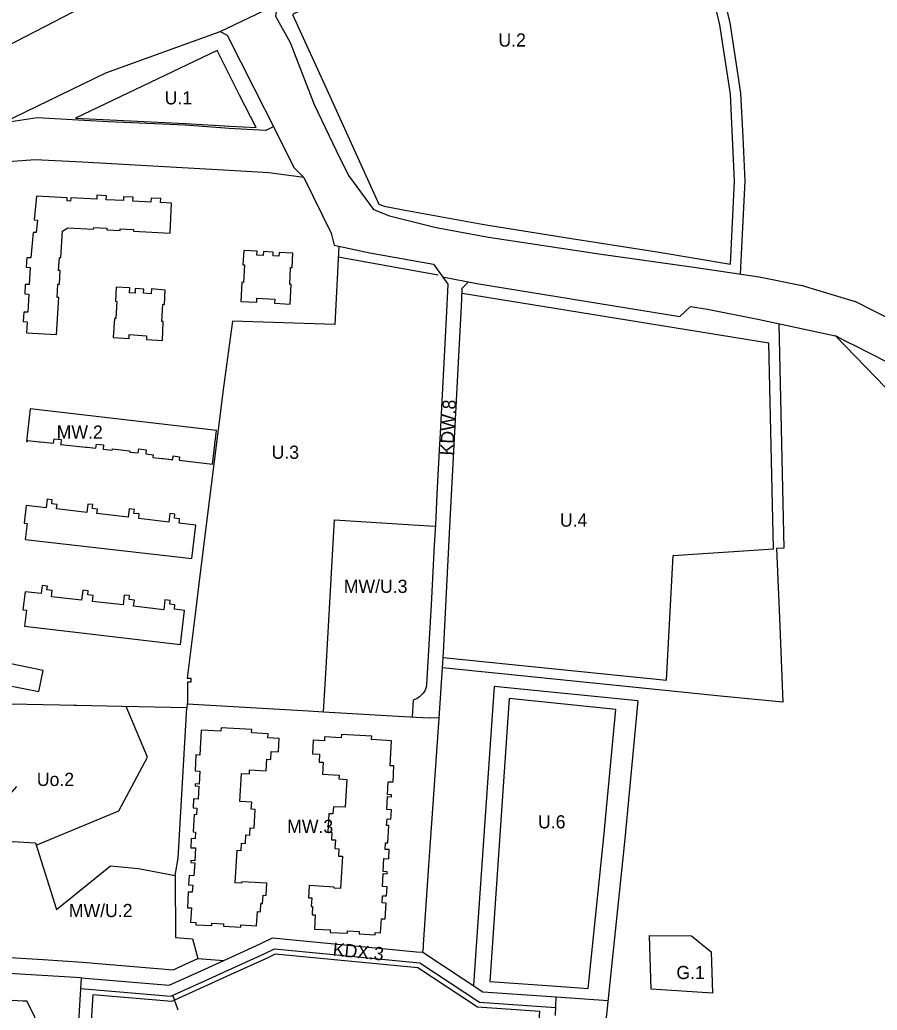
# Model space of a CAD drawing. Extents: x 7427074 to 7428708, y 5545888 to 5547145.
# Drawn here: x 7427562.4 to 7427887.2, y 5546349.6 to 5546725 of the extents above; entities that cross this region are included whole.
import ezdxf

# ---------------------------------------------------------------- set-up
doc = ezdxf.new("R2010")
doc.units = 0
for name, color, linetype in [('linie_rozgraniczajace', 7, 'Continuous'), ('linie_zabudowy_nieprzekraczalne', 7, 'Continuous'), ('linie_zabudowy_obowiazujace', 7, 'Continuous'), ('oznaczenia_przeznaczen', 7, 'Continuous')]:
    doc.layers.add(name, color=color, linetype=linetype)

msp = doc.modelspace()

# ---------------------------------------------------------------- linework, layer by layer
at = {"layer": 'linie_rozgraniczajace'}
for p, q in [((7427655.48, 5546683.03), (7427658.46, 5546684.55)), ((7427729.83, 5546619.05), (7427730.05, 5546623.33)), ((7427735.55, 5546625.11), (7427812.43, 5546612.51)), ((7427725.37, 5546532.76), (7427729.83, 5546619.05)), ((7427715.52, 5546533.36), (7427719.83, 5546533.1)), ((7427793.97, 5546467.06), (7427742.1, 5546472.34)), ((7427577.73, 5546465.23), (7427571.25, 5546465.36)), ((7427583.01, 5546465.12), (7427577.73, 5546465.23)), ((7427583.81, 5546465.1), (7427583.01, 5546465.12)), ((7427600.98, 5546464.74), (7427583.81, 5546465.1)), ((7427711.44, 5546467.07), (7427711.1, 5546460.77)), ((7427796.61, 5546466.79), (7427793.97, 5546467.06)), ((7427625.7, 5546464.21), (7427600.98, 5546464.74)), ((7427622.91, 5546416.05), (7427625.7, 5546464.21)), ((7427715.02, 5546460.56), (7427717.67, 5546460.41)), ((7427721.22, 5546460.22), (7427717.67, 5546460.41)), ((7427622.4, 5546407.21), (7427622.91, 5546416.05)), ((7427621.29, 5546400.65), (7427622.4, 5546407.21)), ((7427576.26, 5546387.77), (7427596.75, 5546404.32)), ((7427596.75, 5546404.32), (7427607.32, 5546403.27)), ((7427607.32, 5546403.27), (7427621.29, 5546400.65)), ((7427658.84, 5546372.88), (7427713.94, 5546367.53)), ((7427712.66, 5546371.67), (7427715.15, 5546371.52)), ((7427715.15, 5546371.52), (7427737.83, 5546356.58)), ((7427713.94, 5546367.53), (7427736.51, 5546352.66)), ((7427585.66, 5546361.85), (7427583.79, 5546331.94)), ((7427572.14, 5546338.65), (7427565.07, 5546353.09)), ((7427622.4, 5546349.58), (7427620.32, 5546355.24)), ((7427765.34, 5546347.61), (7427765.55, 5546354.65))]:
    msp.add_line(p, q, dxfattribs=at)
for points in [[(7427400.2, 5546611.86), (7427442.19, 5546643.82), (7427480.94, 5546671.03), (7427524.86, 5546698.24), (7427615.03, 5546744.99), (7427747.54, 5546812.47), (7427897.12, 5546887.45), (7428084.42, 5546980.69), (7428179.45, 5547028.08)], [(7427638.36, 5546720.62), (7427657.58, 5546729.8), (7427659.95, 5546730.93), (7427768.59, 5546782.79), (7427797.99, 5546801.02), (7427860.58, 5546832.47), (7427996.31, 5546900.83), (7428036.08, 5546920.85), (7428083.92, 5546944.95), (7428147.58, 5546977.01), (7428190.12, 5546998.43)], [(7427835.49, 5546628.61), (7427836.35, 5546646.31), (7427837.2, 5546663.8), (7427836.41, 5546680.51), (7427835.63, 5546697.23), (7427833.57, 5546710.55), (7427831.52, 5546723.86), (7427827.87, 5546739.27), (7427824.22, 5546754.69), (7427820.57, 5546770.1), (7427816.92, 5546785.51), (7427810.97, 5546807.54)], [(7427659.95, 5546730.93), (7427659.28, 5546726.41), (7427664.87, 5546716.42), (7427673.88, 5546692.97), (7427682.3, 5546675.51), (7427686.9, 5546666), (7427696.35, 5546653.1), (7427702.46, 5546650.69), (7427720.19, 5546646.26), (7427739.95, 5546642.68), (7427782.69, 5546636.21), (7427817.72, 5546631.23), (7427842.55, 5546627.57), (7427858.78, 5546624.29), (7427878.85, 5546618.23)], [(7427364.2, 5546554.17), (7427395.05, 5546577.83), (7427421.52, 5546598.13), (7427443.89, 5546615.25), (7427461.19, 5546627.88), (7427476.45, 5546638.44), (7427486.49, 5546645.1), (7427491.66, 5546648.44), (7427499.68, 5546653.51), (7427507.23, 5546658.17), (7427516.35, 5546663.63), (7427526.34, 5546669.42), (7427534.09, 5546673.78), (7427540.36, 5546677.22), (7427550.02, 5546682.6), (7427555.89, 5546685.9), (7427594.96, 5546704.86), (7427638.36, 5546720.62)], [(7427638.36, 5546720.62), (7427640.95, 5546719.15), (7427651, 5546699.2), (7427659.1, 5546683.29)], [(7427655.48, 5546683.03), (7427641.71, 5546683.78), (7427625.07, 5546685.04), (7427596.01, 5546686.32), (7427586.83, 5546686.79), (7427569.02, 5546687.86), (7427555.86, 5546685.88)], [(7427659.1, 5546683.29), (7427666.24, 5546669.07), (7427670.02, 5546665.3), (7427680.36, 5546644.15), (7427681.53, 5546639.53)], [(7427670.02, 5546665.3), (7427656.69, 5546667.04), (7427641.81, 5546667.88), (7427623.85, 5546668.9), (7427585.97, 5546670.99), (7427568.18, 5546671.93), (7427549.37, 5546670.57), (7427543.89, 5546667.66), (7427525, 5546659.31), (7427503.72, 5546645.77), (7427469.2, 5546620.79), (7427458.78, 5546615.05), (7427424.98, 5546588.18), (7427381.06, 5546554.49)], [(7427683.22, 5546639.18), (7427681.71, 5546609.54), (7427642.94, 5546610.74), (7427639.58, 5546585.77), (7427634.91, 5546548.56), (7427630.5, 5546513.34), (7427628.92, 5546500.76), (7427625.74, 5546475.42), (7427627.14, 5546475.48), (7427627.2, 5546473.98), (7427625.9, 5546473.93), (7427625.87, 5546466.07), (7427625.84, 5546465.71), (7427625.7, 5546464.21)], [(7427681.53, 5546639.53), (7427694.95, 5546636.74), (7427719.07, 5546632.44), (7427724.6, 5546624.85)], [(7427722.6, 5546627.6), (7427735.55, 5546625.11)], [(7427724.6, 5546624.85), (7427723.94, 5546611.92), (7427721.55, 5546565.94), (7427721.45, 5546564.3), (7427720.44, 5546545.17), (7427719.86, 5546533.63), (7427719.36, 5546525.82), (7427718.19, 5546503.3), (7427716.54, 5546473.03), (7427716.36, 5546471.86), (7427715.79, 5546470.67), (7427715.22, 5546469.82), (7427714.58, 5546469.09), (7427713.86, 5546468.36), (7427712.91, 5546467.7), (7427711.44, 5546467.07)], [(7427730.05, 5546623.33), (7427732.42, 5546625.71)], [(7427812.43, 5546612.51), (7427816.54, 5546616.39), (7427822.91, 5546615.31)], [(7427822.91, 5546615.31), (7427842.03, 5546611.49), (7427871.42, 5546605.18), (7427894.13, 5546581.67)], [(7427946.45, 5546578.21), (7427924.84, 5546593.37), (7427918.6, 5546597.94), (7427906.55, 5546604.1), (7427890.37, 5546612.47), (7427886.58, 5546614.33), (7427878.85, 5546618.23)], [(7427849.96, 5546609.79), (7427851.93, 5546524.74), (7427849.13, 5546524.54), (7427850.22, 5546498.26), (7427851.55, 5546466.3)], [(7427936.76, 5546566.69), (7427916.1, 5546581.17), (7427910.7, 5546585.13), (7427907.42, 5546586.81), (7427899.69, 5546590.77), (7427883.62, 5546599.07), (7427879.89, 5546600.9), (7427875.47, 5546603.13), (7427871.42, 5546605.18)], [(7427677.45, 5546462.71), (7427678.15, 5546475.19), (7427678.53, 5546481.64), (7427681.66, 5546535.43), (7427715.52, 5546533.36)], [(7427721.22, 5546460.22), (7427722.53, 5546479.36), (7427722.92, 5546485.17), (7427725.37, 5546532.76)], [(7427851.55, 5546466.3), (7427827.82, 5546468.68), (7427794.47, 5546472.03), (7427722.53, 5546479.36)], [(7427742.1, 5546472.34), (7427735.1, 5546370.15), (7427734.33, 5546358.89)], [(7427571.25, 5546465.36), (7427558.99, 5546465.62), (7427552.3, 5546465.76), (7427547.71, 5546446.24)], [(7427625.84, 5546465.71), (7427671.82, 5546463.04), (7427677.45, 5546462.71), (7427707.88, 5546460.95), (7427715.02, 5546460.56)], [(7427796.61, 5546466.79), (7427791.59, 5546414.49), (7427783.21, 5546333.36)], [(7427715.15, 5546371.52), (7427715.28, 5546373.4), (7427715.35, 5546374.48), (7427717.4, 5546404.44), (7427717.88, 5546411.51), (7427721.22, 5546460.22)], [(7427557.29, 5546413.6), (7427568.29, 5546413.01), (7427576.26, 5546387.77)], [(7427621.29, 5546400.65), (7427621.43, 5546377.11), (7427627.81, 5546376.68), (7427629.81, 5546369.13)], [(7427639.63, 5546368.43), (7427653.51, 5546374.75), (7427658.11, 5546376.97)], [(7427658.11, 5546376.97), (7427712.66, 5546371.67)], [(7427641.29, 5546364.79), (7427655.21, 5546371.13), (7427658.84, 5546372.88)], [(7427585.66, 5546361.85), (7427618.94, 5546359.01), (7427631.05, 5546364.53), (7427639.63, 5546368.43)], [(7427629.81, 5546369.13), (7427639.63, 5546368.43)], [(7427585.66, 5546361.85), (7427570.85, 5546362.75), (7427543.53, 5546364.4), (7427537.12, 5546364.79)], [(7427585.41, 5546357.86), (7427619.64, 5546354.94), (7427632.71, 5546360.89), (7427641.29, 5546364.79)], [(7427737.83, 5546356.58), (7427765.55, 5546354.65), (7427785.27, 5546353.27)], [(7427535.29, 5546354.89), (7427542.92, 5546354.42), (7427563.55, 5546353.18), (7427565.07, 5546353.09)], [(7427736.51, 5546352.66), (7427765.43, 5546350.65)]]:
    msp.add_lwpolyline(points, dxfattribs=at)
msp.add_lwpolyline([(7427801.59, 5546357.56), (7427800.91, 5546377.85), (7427816.85, 5546377.8), (7427824.29, 5546371.7), (7427824.82, 5546356.06)], close=True, dxfattribs=at)
at = {"layer": 'linie_zabudowy_nieprzekraczalne'}
for p, q in [((7427846.13, 5546602.48), (7427729.94, 5546621.23)), ((7427620.52, 5546364.9), (7427629.81, 5546369.13))]:
    msp.add_line(p, q, dxfattribs=at)
for points in [[(7427831.67, 5546632.42), (7427833.19, 5546663.8), (7427832.42, 5546680.32), (7427831.64, 5546696.83), (7427827.59, 5546723.09), (7427813.04, 5546784.53), (7427809.97, 5546795.89)], [(7427679.2, 5546697.42), (7427698.43, 5546655.1)], [(7427583.51, 5546687.79), (7427625.15, 5546685.67), (7427642.06, 5546684.75), (7427651.94, 5546684.13)], [(7427698.43, 5546655.1), (7427700.43, 5546654.33), (7427706.98, 5546653.15), (7427737.6, 5546647.5)], [(7427737.6, 5546647.5), (7427740.54, 5546647), (7427771.36, 5546642.14), (7427790.85, 5546639.05), (7427804.67, 5546636.9), (7427831.67, 5546632.42)], [(7427720.86, 5546628.2), (7427683.01, 5546635.04)], [(7427847.94, 5546524.46), (7427846.13, 5546602.48)], [(7427807.47, 5546474.74), (7427810, 5546521.95), (7427847.94, 5546524.46)], [(7427722.79, 5546483.25), (7427807.47, 5546474.74)], [(7427747.8, 5546467.74), (7427741.09, 5546369.74), (7427740.45, 5546360.41)], [(7427788.27, 5546463.62), (7427747.8, 5546467.74)], [(7427610.74, 5546445.44), (7427602.71, 5546464.7)], [(7427777.69, 5546357.81), (7427783.63, 5546415.28), (7427788.27, 5546463.62)], [(7427568.55, 5546412.18), (7427599.9, 5546425.12), (7427610.74, 5546445.44)], [(7427561.18, 5546434.41), (7427557.61, 5546430.3), (7427553.76, 5546426.43), (7427545.39, 5546418.04), (7427542.51, 5546414.93), (7427539.47, 5546410.51), (7427536.21, 5546405.47), (7427527.39, 5546393.51), (7427522.96, 5546387.21), (7427516.68, 5546377.54), (7427538.22, 5546370.74), (7427543.89, 5546370.39), (7427571.22, 5546368.74), (7427586.1, 5546367.84), (7427620.52, 5546364.9)], [(7427751.37, 5546290.13), (7427756.55, 5546320.62), (7427757.64, 5546326.33), (7427758.11, 5546329.95), (7427758.57, 5546336.83), (7427758.82, 5546340.34), (7427759.43, 5546349.06), (7427735.84, 5546350.7), (7427713.25, 5546365.58), (7427659.2, 5546370.84), (7427656.06, 5546369.32), (7427642.12, 5546362.97), (7427642.11, 5546362.97), (7427633.54, 5546359.07), (7427621.01, 5546353.36), (7427620, 5546352.9), (7427590.07, 5546355.46), (7427588.43, 5546329.27)], [(7427740.45, 5546360.41), (7427765.83, 5546358.64), (7427777.69, 5546357.81)]]:
    msp.add_lwpolyline(points, dxfattribs=at)
at = {"layer": 'linie_zabudowy_obowiazujace'}
for p, q in [((7427635.42, 5546556.52), (7427636.9, 5546569.39)), ((7427622.71, 5546558.03), (7427635.42, 5546556.52))]:
    msp.add_line(p, q, dxfattribs=at)
for points in [[(7427809.97, 5546795.89), (7427665.74, 5546727.05), (7427679.2, 5546697.42)], [(7427651.94, 5546684.13), (7427645.65, 5546696.49), (7427637.14, 5546713.39), (7427583.51, 5546687.79)], [(7427636.9, 5546569.39), (7427566.32, 5546577.58), (7427564.88, 5546565.17), (7427565.26, 5546565.13), (7427565.32, 5546565.58), (7427569.79, 5546565.06), (7427570.22, 5546565.04), (7427575.17, 5546564.47), (7427575.36, 5546566.17), (7427578.07, 5546565.86), (7427577.88, 5546564.14), (7427577.86, 5546564.05), (7427577.99, 5546564.04), (7427587.45, 5546562.95), (7427587.86, 5546563), (7427591.22, 5546562.61), (7427591.41, 5546564.19), (7427594.11, 5546563.88), (7427593.93, 5546562.3), (7427593.92, 5546562.22), (7427593.99, 5546562.21), (7427597.39, 5546561.82), (7427597.46, 5546562.41), (7427603.85, 5546561.67), (7427604.19, 5546561.17), (7427607.28, 5546560.81), (7427607.46, 5546562.35), (7427610.29, 5546562.02), (7427610.11, 5546560.49), (7427612.94, 5546560.16), (7427612.82, 5546559.12), (7427616.34, 5546558.71), (7427616.75, 5546558.67), (7427619.77, 5546558.32), (7427620.35, 5546558.28), (7427620.51, 5546559.69), (7427622.87, 5546559.41), (7427622.71, 5546558.03)]]:
    msp.add_lwpolyline(points, dxfattribs=at)
for points in [[(7427619.31, 5546644.18), (7427619.88, 5546655.56), (7427615.69, 5546655.77), (7427615.76, 5546657.27), (7427612.17, 5546657.45), (7427612.09, 5546655.95), (7427605.25, 5546656.3), (7427605.33, 5546657.79), (7427601.73, 5546657.97), (7427601.66, 5546656.48), (7427595.11, 5546656.8), (7427595.19, 5546658.3), (7427591.6, 5546658.48), (7427591.52, 5546656.99), (7427581.67, 5546657.48), (7427581.61, 5546656.28), (7427580.31, 5546656.35), (7427580.37, 5546657.55), (7427568.72, 5546658.13), (7427567.87, 5546649.17), (7427569.06, 5546649.06), (7427568.61, 5546644.33), (7427567.42, 5546644.45), (7427566.5, 5546634.78), (7427565, 5546634.84), (7427564.84, 5546631.24), (7427566.34, 5546631.17), (7427565.97, 5546624.63), (7427564.47, 5546624.72), (7427564.27, 5546621.12), (7427565.77, 5546621.04), (7427565.38, 5546614.15), (7427563.89, 5546614.23), (7427563.68, 5546610.64), (7427565.18, 5546610.55), (7427564.94, 5546606.36), (7427576.33, 5546605.72), (7427577.11, 5546619.7), (7427576.51, 5546619.73), (7427576.8, 5546624.82), (7427577.4, 5546624.79), (7427577.69, 5546629.93), (7427577.09, 5546629.96), (7427577.37, 5546634.96), (7427577.97, 5546634.92), (7427578.53, 5546644.91), (7427580.56, 5546646.19), (7427590.34, 5546645.68), (7427590.37, 5546646.28), (7427595.37, 5546646.03), (7427595.34, 5546645.43), (7427600.43, 5546645.17), (7427600.46, 5546645.77), (7427605.45, 5546645.51), (7427605.42, 5546644.91)], [(7427646.18, 5546618.26), (7427652.16, 5546617.93), (7427652.24, 5546619.44), (7427658.99, 5546619.08), (7427658.9, 5546617.59), (7427664.87, 5546617.27), (7427665.26, 5546624.65), (7427664.66, 5546624.68), (7427665, 5546631.12), (7427665.6, 5546631.09), (7427665.89, 5546636.52), (7427660.67, 5546636.8), (7427660.59, 5546635.36), (7427658.34, 5546635.48), (7427658.42, 5546636.98), (7427654.7, 5546637.17), (7427654.62, 5546635.63), (7427652.24, 5546635.76), (7427652.32, 5546637.25), (7427647.23, 5546637.52), (7427646.94, 5546632.12), (7427647.48, 5546632.09), (7427647.13, 5546625.48), (7427646.57, 5546625.51)], [(7427616.41, 5546603.4), (7427616.76, 5546610.62), (7427616.16, 5546610.65), (7427616.58, 5546617.19), (7427617.18, 5546617.15), (7427617.52, 5546622.54), (7427612.31, 5546622.99), (7427612.11, 5546621.2), (7427609.31, 5546621.38), (7427609.4, 5546622.95), (7427606.14, 5546623.15), (7427606.04, 5546621.45), (7427603.96, 5546621.58), (7427604.07, 5546623.4), (7427598.93, 5546623.72), (7427598.6, 5546618.33), (7427599.2, 5546618.29), (7427598.8, 5546611.8), (7427598.2, 5546611.84), (7427597.75, 5546604.55), (7427603.79, 5546604.18), (7427603.88, 5546605.68), (7427610.42, 5546605.27), (7427610.33, 5546603.78)], [(7427564.79, 5546540.94), (7427564.02, 5546534.23), (7427565.21, 5546534.09), (7427564.43, 5546528.02), (7427627.62, 5546520.77), (7427629.07, 5546533.41), (7427622.76, 5546534.16), (7427622.95, 5546535.83), (7427620.96, 5546536.05), (7427621.14, 5546537.64), (7427619.22, 5546537.86), (7427618.84, 5546534.61), (7427607.43, 5546535.99), (7427607.62, 5546537.68), (7427605.64, 5546537.91), (7427605.81, 5546539.41), (7427603.85, 5546539.64), (7427603.49, 5546536.46), (7427591.63, 5546537.82), (7427591.82, 5546539.51), (7427589.84, 5546539.73), (7427590.01, 5546541.24), (7427588.1, 5546541.46), (7427587.74, 5546538.28), (7427576.31, 5546539.59), (7427576.51, 5546541.28), (7427574.52, 5546541.51), (7427574.69, 5546543.02), (7427572.7, 5546543.25), (7427572.34, 5546540.07)], [(7427564.39, 5546508.21), (7427563.59, 5546501.33), (7427564.91, 5546501.18), (7427564.21, 5546495.17), (7427623.33, 5546488.26), (7427624.82, 5546501.12), (7427620.98, 5546501.57), (7427621.18, 5546503.26), (7427619.17, 5546503.49), (7427619.34, 5546504.94), (7427617.37, 5546505.17), (7427616.94, 5546501.41), (7427605.52, 5546502.73), (7427605.79, 5546504.99), (7427603.76, 5546505.23), (7427603.93, 5546506.73), (7427601.94, 5546506.96), (7427601.5, 5546503.19), (7427589.87, 5546504.54), (7427590.13, 5546506.84), (7427588.14, 5546507.07), (7427588.32, 5546508.57), (7427586.26, 5546508.81), (7427585.81, 5546505), (7427574.43, 5546506.33), (7427574.7, 5546508.63), (7427572.68, 5546508.87), (7427572.85, 5546510.37), (7427570.85, 5546510.6), (7427570.49, 5546507.5)], [(7427558.33, 5546480.99), (7427556.71, 5546472.91), (7427569.59, 5546470.33), (7427571.21, 5546478.41)], [(7427638.71, 5546456.6), (7427638.61, 5546455.35), (7427631.15, 5546455.78), (7427630.61, 5546446.29), (7427629.11, 5546446.36), (7427628.79, 5546440.3), (7427630.6, 5546440.2), (7427630.31, 5546435.27), (7427628.82, 5546435.36), (7427628.8, 5546434.61), (7427630.27, 5546434.54), (7427630.01, 5546429.62), (7427628.21, 5546429.7), (7427628.01, 5546426.26), (7427629.5, 5546426.19), (7427629.37, 5546423.67), (7427628.45, 5546423.71), (7427628.09, 5546417.16), (7427628.99, 5546417.09), (7427628.86, 5546414.58), (7427627.37, 5546414.65), (7427627.16, 5546411.19), (7427628.96, 5546411.09), (7427628.69, 5546406.19), (7427627.2, 5546406.28), (7427627.15, 5546405.51), (7427628.65, 5546405.43), (7427628.36, 5546400.52), (7427626.55, 5546400.63), (7427626.36, 5546397.11), (7427627.88, 5546397.01), (7427627.7, 5546394.29), (7427626.2, 5546394.38), (7427625.89, 5546388.42), (7427627.39, 5546388.33), (7427627.08, 5546382.99), (7427629.07, 5546382.88), (7427629.03, 5546381.98), (7427635.12, 5546381.65), (7427635.13, 5546382.56), (7427639.56, 5546382.29), (7427639.53, 5546381.39), (7427646.07, 5546381.04), (7427646.11, 5546381.92), (7427652.11, 5546381.57), (7427652.41, 5546386.93), (7427653.61, 5546386.86), (7427653.77, 5546390), (7427654.38, 5546389.98), (7427654.56, 5546393.18), (7427655.76, 5546393.12), (7427656.02, 5546397.7), (7427646.45, 5546398.24), (7427646.43, 5546397.74), (7427644.01, 5546397.89), (7427644.7, 5546410.19), (7427646.2, 5546410.1), (7427646.35, 5546412.85), (7427647.85, 5546412.78), (7427648.04, 5546416.02), (7427649.54, 5546415.94), (7427649.69, 5546418.67), (7427651.18, 5546418.59), (7427651.6, 5546425.66), (7427650.09, 5546425.73), (7427650.26, 5546428.49), (7427645.75, 5546428.73), (7427646.36, 5546439.3), (7427649.35, 5546439.15), (7427649.43, 5546440.64), (7427655.73, 5546440.28), (7427655.95, 5546444.76), (7427657.48, 5546444.67), (7427657.64, 5546447.69), (7427660.35, 5546447.54), (7427660.6, 5546452.62), (7427656.42, 5546452.84), (7427656.5, 5546454.36), (7427650.21, 5546454.68), (7427650.28, 5546455.95)], [(7427684.22, 5546454.04), (7427684.15, 5546452.81), (7427677.84, 5546453.16), (7427677.77, 5546451.67), (7427673.56, 5546451.9), (7427673.28, 5546446.82), (7427675.99, 5546446.66), (7427675.81, 5546443.65), (7427677.32, 5546443.58), (7427677.08, 5546439.08), (7427683.35, 5546438.73), (7427683.28, 5546437.23), (7427686.26, 5546437.07), (7427685.68, 5546426.49), (7427681.19, 5546426.73), (7427681.03, 5546423.99), (7427679.53, 5546424.06), (7427679.11, 5546417.01), (7427680.61, 5546416.93), (7427680.44, 5546414.19), (7427681.94, 5546414.11), (7427681.76, 5546410.88), (7427683.27, 5546410.79), (7427683.12, 5546408.03), (7427684.59, 5546407.94), (7427683.91, 5546395.66), (7427681.5, 5546395.78), (7427681.54, 5546396.27), (7427672, 5546396.81), (7427671.71, 5546392.23), (7427672.98, 5546392.17), (7427672.72, 5546388.93), (7427673.32, 5546388.9), (7427673.14, 5546385.74), (7427674.35, 5546385.68), (7427674.04, 5546380.34), (7427680.03, 5546379.99), (7427679.98, 5546379.08), (7427686.54, 5546378.73), (7427686.6, 5546379.61), (7427690.99, 5546379.36), (7427690.93, 5546378.47), (7427697.03, 5546378.14), (7427697.09, 5546379.05), (7427699.09, 5546378.95), (7427699.38, 5546384.25), (7427700.88, 5546384.19), (7427701.18, 5546390.18), (7427699.69, 5546390.26), (7427699.86, 5546392.95), (7427701.37, 5546392.87), (7427701.57, 5546396.4), (7427699.78, 5546396.51), (7427700.04, 5546401.4), (7427701.52, 5546401.32), (7427701.57, 5546402.06), (7427700.08, 5546402.14), (7427700.35, 5546407.07), (7427702.16, 5546406.98), (7427702.36, 5546410.45), (7427700.85, 5546410.54), (7427701, 5546413.04), (7427701.89, 5546413), (7427702.26, 5546419.56), (7427701.36, 5546419.62), (7427701.52, 5546422.14), (7427703, 5546422.05), (7427703.19, 5546425.51), (7427701.39, 5546425.6), (7427701.69, 5546430.54), (7427703.18, 5546430.46), (7427703.2, 5546431.21), (7427701.73, 5546431.29), (7427701.99, 5546436.17), (7427703.79, 5546436.09), (7427704.14, 5546442.16), (7427702.65, 5546442.23), (7427703.17, 5546451.73), (7427695.69, 5546452.15), (7427695.76, 5546453.4)]]:
    msp.add_lwpolyline(points, close=True, dxfattribs=at)

# ---------------------------------------------------------------- texts
at = {"layer": 'oznaczenia_przeznaczen'}
for s, p in [('U.2', (7427743.74, 5546714.86)), ('U.1', (7427617.29, 5546692.94)), ('MW.2', (7427576.35, 5546566.23)), ('U.3', (7427657.79, 5546558.6)), ('U.4', (7427767, 5546532.87)), ('MW/U.3', (7427685.13, 5546507.77)), ('Uo.2', (7427568.83, 5546434.57)), ('MW.3', (7427663.68, 5546416.75)), ('U.6', (7427758.74, 5546418.49)), ('MW/U.2', (7427580.96, 5546384.86)), ('G.1', (7427811.17, 5546361.37))]:
    msp.add_text(s, height=5, dxfattribs=at).set_placement(p)
for s, rotation, p in [('KDW.8', 87.1199, (7427726.6, 5546559.77)), ('KDX.3', 354.3584, (7427680.8, 5546370.27))]:
    msp.add_text(s, height=5, rotation=rotation, dxfattribs=at).set_placement(p)

doc.saveas('drawing.dxf')
